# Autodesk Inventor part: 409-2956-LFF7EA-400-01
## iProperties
Created: 2010-06
Part Number: 409-2956-LFF7EA-400-01
Material: 1/16"Thk PLASTIC
Document SubType Name: Modeling
Designer: S. Boerckel
Engineer: Steve Boerckel
Mass: 230.369 g
Surface Area: 3121.56 cm^2
Volume: 245.074 cm^3
Density: 0.94 g/cm^3
Description: TAG
SMR: =<Material>
Length: 20.000 in
Wide: 12.000 in
Thickness: 0.063 in
Author: S. Boerckel
Revision Number: 0
Subject: DEMIN WATER FORWARDING PUMP SKID-7EA
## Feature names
1. Extrusion1
2. Hole1
